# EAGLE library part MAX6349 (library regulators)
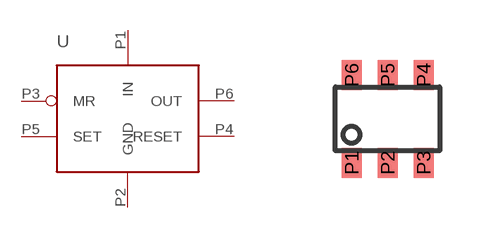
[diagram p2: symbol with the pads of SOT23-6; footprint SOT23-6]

Designator prefix U

## MAX6349  [SOT23-6]
P1  IN  pwr
P2  GND  pwr
P3  MR  in
P4  RESET  out
P5  SET  in
P6  OUT  pwr

## Footprint SOT23-6 (pad centres in mm)
smd 0.5 x 0.75: P1 -0.9,-1.1; P2 0,-1.1; P3 0.9,-1.1; P4 0.9,1.1; P5 0,1.1; P6 -0.9,1.1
